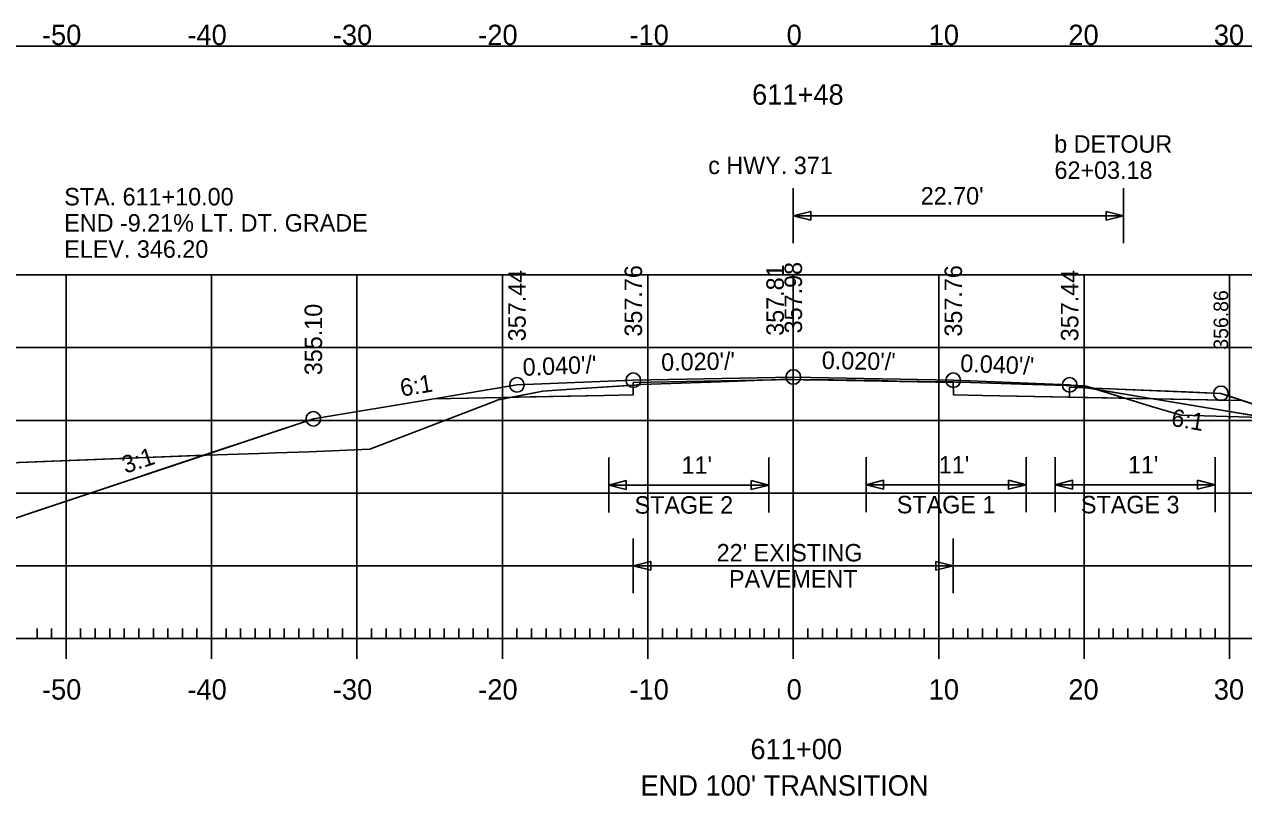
# Model space of a CAD drawing. Extents: x 1368910 to 1369601, y 380116 to 380950.
# Drawn here: x 1369384.7 to 1369468.6, y 380363.1 to 380416.6 of the extents above; entities that cross this region are included whole.
import ezdxf

# ---------------------------------------------------------------- set-up
doc = ezdxf.new("R2010")
doc.units = 0
for name, color, linetype in [('_STAGE 1 CUT', 7, 'Continuous'), ('_STAGE 2 CUT', 7, 'Continuous'), ('_STAGE 2 FILL', 7, 'Continuous'), ('_STAGE 4 CUT', 7, 'Continuous'), ('Notes', 7, 'Continuous'), ('R_Alt Surface', 7, 'Continuous'), ('R_Axis', 7, 'Continuous'), ('R_Axis Annot', 7, 'Continuous'), ('R_Detour Surface', 7, 'Continuous'), ('R_Exist Surface', 7, 'Continuous'), ('R_Fin Surface', 7, 'Continuous'), ('R_Grid', 7, 'Continuous'), ('R_No Plot', 7, 'Continuous'), ('R_ROW Annot', 7, 'Continuous'), ('R_Xsect Elev', 7, 'Continuous'), ('R_Xsect Elev Detour', 7, 'Continuous'), ('R_Xsect Slope', 7, 'Continuous')]:
    doc.layers.add(name, color=color, linetype=linetype)

msp = doc.modelspace()

# ---------------------------------------------------------------- linework, layer by layer
at = {"layer": '_STAGE 1 CUT'}
for p, q in [((1369417.59, 380390.999), (1369412.863, 380390.904)), ((1369417.59, 380390.886), (1369418.232, 380391.011)), ((1369418.232, 380391.011), (1369417.59, 380390.999)), ((1369417.59, 380390.999), (1369417.59, 380390.886)), ((1369417.59, 380390.886), (1369417.59, 380390.999)), ((1369418.232, 380391.011), (1369424.59, 380391.139))]:
    msp.add_line(p, q, dxfattribs=at)
for points in [[(1369426.588, 380391.844), (1369422.641, 380391.591), (1369420.368, 380391.429), (1369418.232, 380391.011)], [(1369424.59, 380391.139), (1369426.58, 380391.179), (1369426.588, 380391.844)], [(1369412.863, 380390.904), (1369404.59, 380389.525), (1369397.063, 380387.016)], [(1369397.063, 380387.016), (1369397.235, 380387.023), (1369400.874, 380387.131), (1369402.031, 380387.181), (1369404.28, 380387.266), (1369408.474, 380387.429), (1369417.025, 380390.718), (1369417.347, 380390.844), (1369417.454, 380390.86), (1369417.59, 380390.886)], [(1369397.063, 380387.016), (1369371.53, 380386.029), (1369368.73, 380385.899), (1369366.159, 380385.045)], [(1369376.64, 380381.542), (1369380.64, 380381.542), (1369397.063, 380387.016)]]:
    msp.add_lwpolyline(points, dxfattribs=at)
at = {"layer": '_STAGE 2 CUT'}
for p, q in [((1369448.59, 380392.057), (1369448.59, 380392.012)), ((1369456.59, 380391.019), (1369460.391, 380390.943))]:
    msp.add_line(p, q, dxfattribs=at)
for points in [[(1369460.391, 380390.943), (1369458.444, 380391.55), (1369458.193, 380391.628), (1369457.636, 380391.801), (1369457.131, 380391.826), (1369456.829, 380391.819), (1369456.352, 380391.807), (1369453.288, 380391.906), (1369449.052, 380392.042), (1369448.775, 380392.05), (1369448.59, 380392.057)], [(1369448.59, 380392.012), (1369448.6, 380391.179), (1369450.59, 380391.139), (1369456.59, 380391.019)], [(1369456.59, 380391.019), (1369456.59, 380391.019)]]:
    msp.add_lwpolyline(points, dxfattribs=at)
at = {"layer": '_STAGE 2 FILL'}
for p, q in [((1369462.317, 380390.904), (1369460.391, 380390.943)), ((1369468.475, 380390.781), (1369462.317, 380390.904)), ((1369472.641, 380389.392), (1369468.475, 380390.781))]:
    msp.add_line(p, q, dxfattribs=at)
for points in [[(1369460.391, 380390.943), (1369462.207, 380390.376), (1369464.261, 380389.768), (1369468.213, 380389.665), (1369469.829, 380389.624), (1369470.105, 380389.606), (1369472.152, 380389.472), (1369472.641, 380389.392)], [(1369462.317, 380390.904), (1369462.317, 380390.904)]]:
    msp.add_lwpolyline(points, dxfattribs=at)
at = {"layer": '_STAGE 4 CUT'}
for p, q in [((1369457.906, 380391.639), (1369458.444, 380391.55)), ((1369458.193, 380391.628), (1369457.906, 380391.639)), ((1369458.193, 380391.628), (1369458.444, 380391.55)), ((1369458.444, 380391.55), (1369458.193, 380391.628))]:
    msp.add_line(p, q, dxfattribs=at)
for points in [[(1369472.555, 380389.421), (1369469.007, 380390.604), (1369467.59, 380391.076), (1369466.99, 380391.276), (1369464.59, 380391.372), (1369458.193, 380391.628)], [(1369458.444, 380391.55), (1369462.317, 380390.904), (1369467.59, 380390.025), (1369470.105, 380389.606), (1369470.59, 380389.525), (1369470.903, 380389.421), (1369477.59, 380387.192), (1369478.654, 380386.837)]]:
    msp.add_lwpolyline(points, dxfattribs=at)
at = {"layer": 'R_Alt Surface'}
for points in [[(1369412.863, 380390.904), (1369424.59, 380391.139), (1369426.58, 380391.179), (1369426.59, 380392.012), (1369437.59, 380392.232), (1369448.59, 380392.012), (1369448.6, 380391.179), (1369450.59, 380391.139), (1369462.317, 380390.904)], [(1369456.59, 380391.692), (1369456.59, 380391.019), (1369468.475, 380390.781)]]:
    msp.add_lwpolyline(points, dxfattribs=at)
at = {"layer": 'R_Axis'}
for p, q in [((1369387.59, 380373.021), (1369387.59, 380375.821)), ((1369397.59, 380373.021), (1369397.59, 380375.821)), ((1369407.59, 380373.021), (1369407.59, 380375.821)), ((1369417.59, 380373.021), (1369417.59, 380375.821)), ((1369427.59, 380373.021), (1369427.59, 380375.821)), ((1369437.59, 380373.021), (1369437.59, 380375.821)), ((1369447.59, 380373.021), (1369447.59, 380375.821)), ((1369457.59, 380373.021), (1369457.59, 380375.821)), ((1369467.59, 380373.021), (1369467.59, 380375.821)), ((1369385.59, 380374.421), (1369385.59, 380375.121)), ((1369386.59, 380374.421), (1369386.59, 380375.121)), ((1369388.59, 380374.421), (1369388.59, 380375.121)), ((1369389.59, 380374.421), (1369389.59, 380375.121)), ((1369390.59, 380374.421), (1369390.59, 380375.121)), ((1369391.59, 380374.421), (1369391.59, 380375.121)), ((1369392.59, 380374.421), (1369392.59, 380375.121)), ((1369393.59, 380374.421), (1369393.59, 380375.121)), ((1369394.59, 380374.421), (1369394.59, 380375.121)), ((1369395.59, 380374.421), (1369395.59, 380375.121)), ((1369396.59, 380374.421), (1369396.59, 380375.121)), ((1369398.59, 380374.421), (1369398.59, 380375.121)), ((1369399.59, 380374.421), (1369399.59, 380375.121)), ((1369400.59, 380374.421), (1369400.59, 380375.121)), ((1369401.59, 380374.421), (1369401.59, 380375.121)), ((1369402.59, 380374.421), (1369402.59, 380375.121)), ((1369403.59, 380374.421), (1369403.59, 380375.121)), ((1369404.59, 380374.421), (1369404.59, 380375.121)), ((1369405.59, 380374.421), (1369405.59, 380375.121)), ((1369406.59, 380374.421), (1369406.59, 380375.121)), ((1369408.59, 380374.421), (1369408.59, 380375.121)), ((1369409.59, 380374.421), (1369409.59, 380375.121)), ((1369410.59, 380374.421), (1369410.59, 380375.121)), ((1369411.59, 380374.421), (1369411.59, 380375.121)), ((1369412.59, 380374.421), (1369412.59, 380375.121)), ((1369413.59, 380374.421), (1369413.59, 380375.121)), ((1369414.59, 380374.421), (1369414.59, 380375.121)), ((1369415.59, 380374.421), (1369415.59, 380375.121)), ((1369416.59, 380374.421), (1369416.59, 380375.121)), ((1369418.59, 380374.421), (1369418.59, 380375.121)), ((1369419.59, 380374.421), (1369419.59, 380375.121)), ((1369420.59, 380374.421), (1369420.59, 380375.121)), ((1369421.59, 380374.421), (1369421.59, 380375.121)), ((1369422.59, 380374.421), (1369422.59, 380375.121)), ((1369423.59, 380374.421), (1369423.59, 380375.121)), ((1369424.59, 380374.421), (1369424.59, 380375.121)), ((1369425.59, 380374.421), (1369425.59, 380375.121)), ((1369426.59, 380374.421), (1369426.59, 380375.121)), ((1369428.59, 380374.421), (1369428.59, 380375.121)), ((1369429.59, 380374.421), (1369429.59, 380375.121)), ((1369430.59, 380374.421), (1369430.59, 380375.121)), ((1369431.59, 380374.421), (1369431.59, 380375.121)), ((1369432.59, 380374.421), (1369432.59, 380375.121)), ((1369433.59, 380374.421), (1369433.59, 380375.121)), ((1369434.59, 380374.421), (1369434.59, 380375.121)), ((1369435.59, 380374.421), (1369435.59, 380375.121)), ((1369436.59, 380374.421), (1369436.59, 380375.121)), ((1369438.59, 380374.421), (1369438.59, 380375.121)), ((1369439.59, 380374.421), (1369439.59, 380375.121)), ((1369440.59, 380374.421), (1369440.59, 380375.121)), ((1369441.59, 380374.421), (1369441.59, 380375.121)), ((1369442.59, 380374.421), (1369442.59, 380375.121)), ((1369443.59, 380374.421), (1369443.59, 380375.121)), ((1369444.59, 380374.421), (1369444.59, 380375.121)), ((1369445.59, 380374.421), (1369445.59, 380375.121)), ((1369446.59, 380374.421), (1369446.59, 380375.121)), ((1369448.59, 380374.421), (1369448.59, 380375.121)), ((1369449.59, 380374.421), (1369449.59, 380375.121)), ((1369450.59, 380374.421), (1369450.59, 380375.121)), ((1369451.59, 380374.421), (1369451.59, 380375.121)), ((1369452.59, 380374.421), (1369452.59, 380375.121)), ((1369453.59, 380374.421), (1369453.59, 380375.121)), ((1369454.59, 380374.421), (1369454.59, 380375.121)), ((1369455.59, 380374.421), (1369455.59, 380375.121)), ((1369456.59, 380374.421), (1369456.59, 380375.121)), ((1369458.59, 380374.421), (1369458.59, 380375.121)), ((1369459.59, 380374.421), (1369459.59, 380375.121)), ((1369460.59, 380374.421), (1369460.59, 380375.121)), ((1369461.59, 380374.421), (1369461.59, 380375.121)), ((1369462.59, 380374.421), (1369462.59, 380375.121)), ((1369463.59, 380374.421), (1369463.59, 380375.121)), ((1369464.59, 380374.421), (1369464.59, 380375.121)), ((1369465.59, 380374.421), (1369465.59, 380375.121)), ((1369466.59, 380374.421), (1369466.59, 380375.121)), ((1369297.59, 380374.421), (1369577.59, 380374.421))]:
    msp.add_line(p, q, dxfattribs=at)
at = {"layer": 'R_Detour Surface'}
msp.add_lwpolyline([(1369456.59, 380391.692), (1369466.99, 380391.276), (1369468.475, 380390.781), (1369480.306, 380386.837)], dxfattribs=at)
at = {"layer": 'R_Exist Surface'}
msp.add_lwpolyline([(1369371.53, 380386.029), (1369397.235, 380387.023), (1369400.874, 380387.131), (1369402.031, 380387.181), (1369404.28, 380387.266), (1369408.474, 380387.429), (1369417.025, 380390.718), (1369417.347, 380390.844), (1369417.454, 380390.86), (1369420.368, 380391.429), (1369422.641, 380391.591), (1369426.685, 380391.85), (1369426.829, 380391.86), (1369427.135, 380391.882), (1369432.583, 380392.075), (1369437.241, 380392.244), (1369437.455, 380392.235), (1369437.548, 380392.233), (1369438.296, 380392.201), (1369440.327, 380392.198), (1369443.492, 380392.155), (1369444.702, 380392.118), (1369447.803, 380392.058), (1369448.548, 380392.058), (1369448.775, 380392.05), (1369449.052, 380392.042), (1369453.288, 380391.906), (1369456.352, 380391.807), (1369457.131, 380391.826), (1369457.636, 380391.801), (1369462.207, 380390.376), (1369464.261, 380389.768), (1369468.213, 380389.665), (1369469.829, 380389.624)], dxfattribs=at)
at = {"layer": 'R_Fin Surface'}
msp.add_lwpolyline([(1369366.149, 380385.039), (1369376.64, 380381.542), (1369380.64, 380381.542), (1369404.59, 380389.525), (1369412.863, 380390.904), (1369418.59, 380391.859), (1369426.59, 380392.179), (1369437.59, 380392.399), (1369448.59, 380392.179), (1369456.59, 380391.859), (1369462.317, 380390.904), (1369470.59, 380389.525), (1369478.654, 380386.837), (1369482.654, 380386.837), (1369492.018, 380389.958)], dxfattribs=at)
at = {"layer": 'R_Grid'}
for p, q in [((1369297.59, 380399.421), (1369577.59, 380399.421)), ((1369387.59, 380374.421), (1369387.59, 380399.421)), ((1369397.59, 380374.421), (1369397.59, 380399.421)), ((1369407.59, 380374.421), (1369407.59, 380399.421)), ((1369417.59, 380374.421), (1369417.59, 380399.421)), ((1369427.59, 380374.421), (1369427.59, 380399.421)), ((1369437.59, 380374.421), (1369437.59, 380399.421)), ((1369447.59, 380374.421), (1369447.59, 380399.421)), ((1369457.59, 380374.421), (1369457.59, 380399.421)), ((1369467.59, 380374.421), (1369467.59, 380399.421)), ((1369297.59, 380394.421), (1369577.59, 380394.421)), ((1369297.59, 380389.421), (1369577.59, 380389.421)), ((1369297.59, 380384.421), (1369577.59, 380384.421)), ((1369297.59, 380379.421), (1369577.59, 380379.421)), ((1369297.59, 380374.421), (1369577.59, 380374.421))]:
    msp.add_line(p, q, dxfattribs=at)
at = {"layer": 'R_No Plot'}
msp.add_lwpolyline([(1369281.59, 380415.151), (1369593.77, 380415.151), (1369593.77, 380316.421), (1369281.59, 380316.421)], close=True, dxfattribs=at)
for centre in [(1369418.59, 380391.859), (1369426.59, 380392.179), (1369437.59, 380392.399), (1369448.59, 380392.179), (1369456.59, 380391.859), (1369466.99, 380391.276), (1369404.59, 380389.525)]:
    msp.add_circle(centre, 0.5, dxfattribs=at)
at = {"layer": 'R_ROW Annot'}
for p, q in [((1369437.59, 380401.602), (1369437.59, 380405.371)), ((1369460.29, 380401.602), (1369460.29, 380405.371)), ((1369460.29, 380403.487), (1369437.59, 380403.487)), ((1369424.899, 380383.09), (1369424.899, 380386.858)), ((1369435.899, 380383.09), (1369435.899, 380386.858)), ((1369442.59, 380383.113), (1369442.59, 380386.881)), ((1369453.59, 380383.113), (1369453.59, 380386.881)), ((1369455.59, 380383.113), (1369455.59, 380386.881)), ((1369466.59, 380383.113), (1369466.59, 380386.881)), ((1369435.899, 380384.974), (1369424.899, 380384.974)), ((1369453.59, 380384.997), (1369442.59, 380384.997)), ((1369466.59, 380384.997), (1369455.59, 380384.997)), ((1369426.59, 380377.537), (1369426.59, 380381.305)), ((1369448.59, 380377.537), (1369448.59, 380381.305)), ((1369448.59, 380379.421), (1369426.59, 380379.421))]:
    msp.add_line(p, q, dxfattribs=at)
for points in [[(1369438.79, 380403.187), (1369437.59, 380403.487), (1369438.79, 380403.787)], [(1369459.09, 380403.787), (1369460.29, 380403.487), (1369459.09, 380403.187)], [(1369426.099, 380384.674), (1369424.899, 380384.974), (1369426.099, 380385.274)], [(1369434.699, 380385.274), (1369435.899, 380384.974), (1369434.699, 380384.674)], [(1369443.79, 380384.697), (1369442.59, 380384.997), (1369443.79, 380385.297)], [(1369452.39, 380385.297), (1369453.59, 380384.997), (1369452.39, 380384.697)], [(1369456.79, 380384.697), (1369455.59, 380384.997), (1369456.79, 380385.297)], [(1369465.39, 380385.297), (1369466.59, 380384.997), (1369465.39, 380384.697)], [(1369427.79, 380379.121), (1369426.59, 380379.421), (1369427.79, 380379.721)], [(1369447.39, 380379.721), (1369448.59, 380379.421), (1369447.39, 380379.121)]]:
    msp.add_lwpolyline(points, close=True, dxfattribs=at)

# ---------------------------------------------------------------- texts
at = {"layer": 'Notes'}
for s, p in [('b DETOUR', (1369455.531, 380407.821)), ('c HWY. 371', (1369431.74, 380406.348)), ('62+03.18', (1369455.549, 380406.021)), ('STA. 611+10.00', (1369387.463, 380404.197)), ('END -9.21% LT. DT. GRADE', (1369387.463, 380402.397)), ('ELEV. 346.20', (1369387.463, 380400.597))]:
    msp.add_text(s, height=1.2, dxfattribs=at).set_placement(p)
at = {"layer": 'R_Axis Annot'}
for s, p in [('-50', (1369385.931, 380415.221)), ('-40', (1369395.931, 380415.221)), ('-30', (1369405.931, 380415.221)), ('-20', (1369415.931, 380415.221)), ('-10', (1369426.328, 380415.221)), ('0', (1369437.132, 380415.221)), ('10', (1369446.901, 380415.221)), ('20', (1369456.504, 380415.221)), ('30', (1369466.504, 380415.221)), ('611+48', (1369434.757, 380411.121)), ('-50', (1369385.931, 380370.221)), ('-40', (1369395.931, 380370.221)), ('-30', (1369405.931, 380370.221)), ('-20', (1369415.931, 380370.221)), ('-10', (1369426.328, 380370.221)), ('0', (1369437.132, 380370.221)), ('10', (1369446.901, 380370.221)), ('20', (1369456.504, 380370.221)), ('30', (1369466.504, 380370.221)), ('611+00', (1369434.641, 380366.121)), ("END 100' TRANSITION", (1369427.079, 380363.621))]:
    msp.add_text(s, height=1.4, dxfattribs=at).set_placement(p)
at = {"layer": 'R_ROW Annot'}
for s, p in [("22.70'", (1369446.351, 380404.256)), ("11'", (1369429.908, 380385.744)), ("11'", (1369447.599, 380385.766)), ("11'", (1369460.599, 380385.766)), ('STAGE 2', (1369426.676, 380383.004)), ('STAGE 1', (1369444.707, 380383.027)), ('STAGE 3', (1369457.367, 380383.027)), ("22' EXISTING", (1369432.322, 380379.721)), ('PAVEMENT', (1369433.173, 380377.921))]:
    msp.add_text(s, height=1.2, dxfattribs=at).set_placement(p)
at = {"layer": 'R_Xsect Elev'}
for s, p in [('357.44', (1369419.19, 380394.859)), ('357.76', (1369427.19, 380395.179)), ('357.81', (1369436.94, 380395.232)), ('357.98', (1369438.19, 380395.399)), ('357.76', (1369449.19, 380395.179)), ('357.44', (1369457.19, 380394.859)), ('355.10', (1369405.19, 380392.525))]:
    msp.add_text(s, height=1.2, rotation=90, dxfattribs=at).set_placement(p)
at = {"layer": 'R_Xsect Elev Detour'}
msp.add_text('356.86', height=1, rotation=90, dxfattribs=at).set_placement((1369467.49, 380394.276))
at = {"layer": 'R_Xsect Slope'}
for s, rotation, p in [("0.040'/'", 2.29061, (1369419.007, 380392.476)), ("0.020'/'", 1.14576, (1369428.516, 380392.817)), ("0.020'/'", 358.85424, (1369439.54, 380392.96)), ("0.040'/'", 357.70939, (1369449.055, 380392.76)), ('6:1', 9.46234, (1369410.66, 380391.044)), ('6:1', 350.53766, (1369463.516, 380389.048)), ('3:1', 18.43493, (1369391.668, 380385.745))]:
    msp.add_text(s, height=1.2, rotation=rotation, dxfattribs=at).set_placement(p)

doc.saveas('drawing.dxf')
